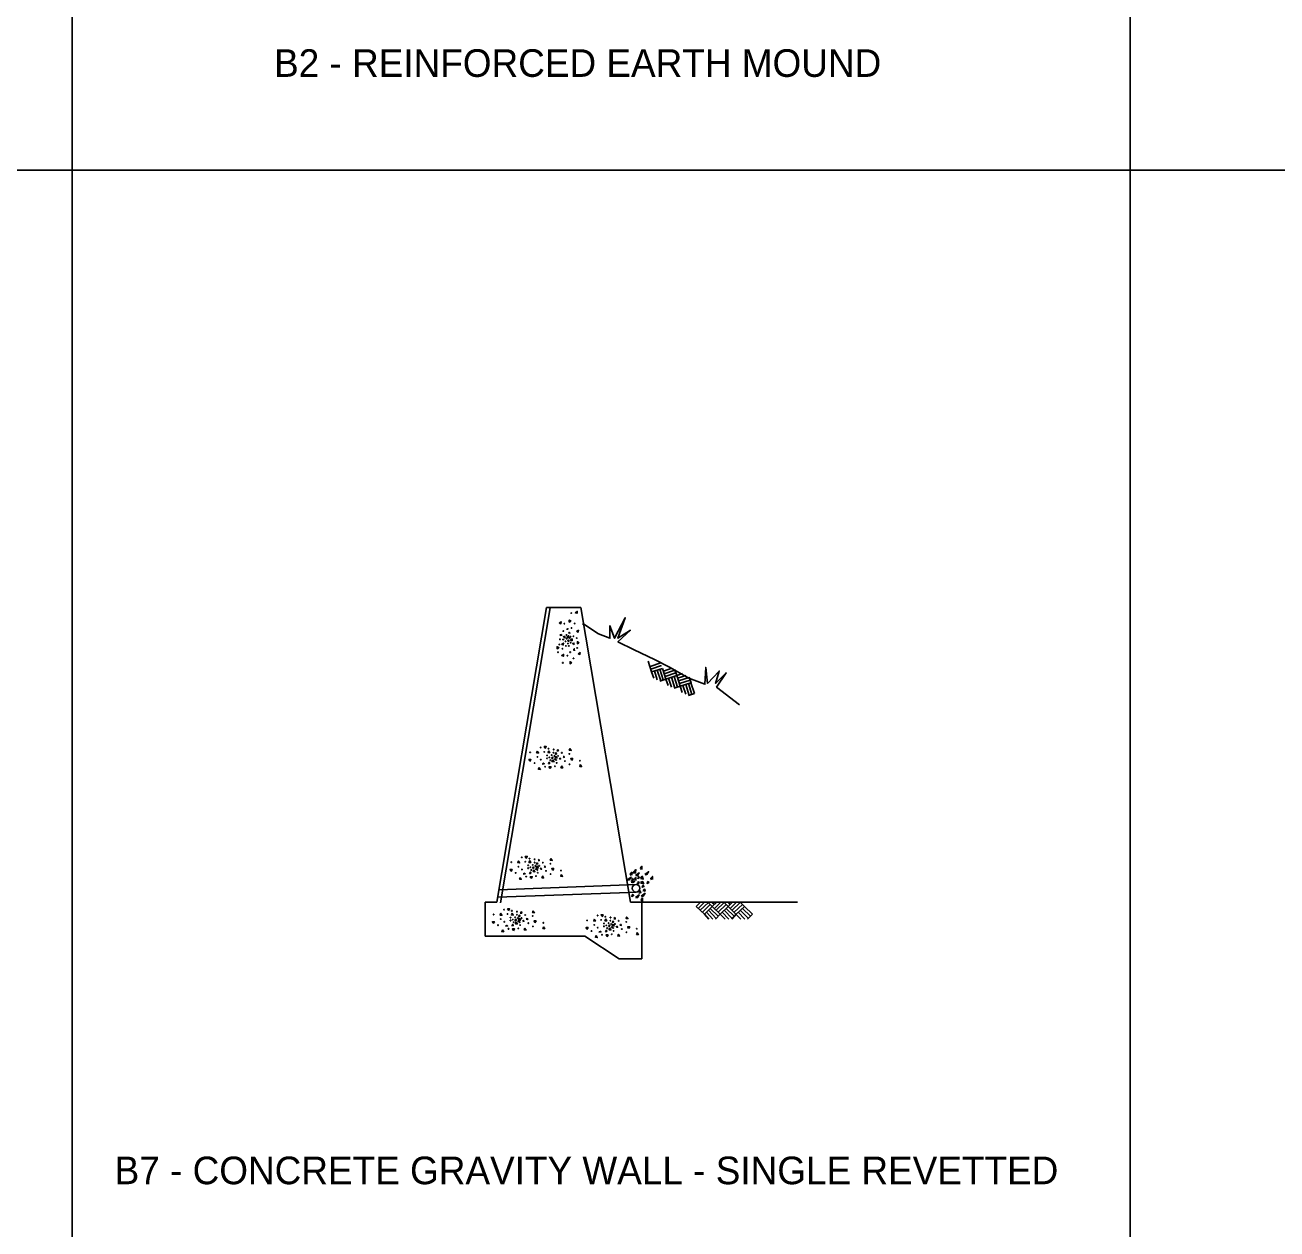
# Model space of a CAD drawing. Extents: x -0.04 to 2.79, y -0.02 to 1.81.
# Drawn here: x 0.5018 to 0.9741, y 0.915 to 1.369 of the extents above; entities that cross this region are included whole.
import ezdxf

# ---------------------------------------------------------------- set-up
doc = ezdxf.new("R2010")
doc.units = 0
doc.layers.add('Level 1', color=7, linetype='Continuous')
doc.layers.add('Level 2', color=7, linetype='Continuous')

msp = doc.modelspace()

# ---------------------------------------------------------------- linework, layer by layer
for p, q in [((0.51951, 1.73185), (0.51951, 0.08028)), ((0.91867, 1.71305), (0.91867, 0.08028)), ((0.11656, 1.31426), (2.51784, 1.31426))]:
    msp.add_line(p, q)
at = {"layer": 'Level 1'}
for p, q in [((0.67974, 1.03828), (0.69847, 1.14941)), ((0.68117, 1.03807), (0.6999, 1.14928)), ((0.69847, 1.14941), (0.71145, 1.14941)), ((0.73018, 1.03828), (0.71145, 1.14941)), ((0.71214, 1.14313), (0.71255, 1.14313)), ((0.73818, 1.12515), (0.73688, 1.12918)), ((0.73756, 1.12713), (0.74159, 1.1285)), ((0.73784, 1.12611), (0.74194, 1.12747)), ((0.73818, 1.12515), (0.74228, 1.12645)), ((0.739, 1.12276), (0.73818, 1.12515)), ((0.7403, 1.12207), (0.7392, 1.12549)), ((0.74159, 1.12173), (0.74023, 1.12576)), ((0.74255, 1.12207), (0.74125, 1.12611)), ((0.74358, 1.12242), (0.74228, 1.12645)), ((0.74262, 1.12542), (0.74576, 1.12652)), ((0.74289, 1.1244), (0.74699, 1.12576)), ((0.74324, 1.12344), (0.74734, 1.12474)), ((0.74768, 1.12371), (0.74693, 1.1259)), ((0.74768, 1.12371), (0.7498, 1.12447)), ((0.74768, 1.12371), (0.7498, 1.12447)), ((0.74125, 1.12166), (0.74358, 1.12242)), ((0.74358, 1.12242), (0.74768, 1.12371)), ((0.7444, 1.12002), (0.74358, 1.12242)), ((0.7457, 1.11941), (0.7446, 1.12276)), ((0.74693, 1.119), (0.74563, 1.1231)), ((0.74795, 1.11934), (0.74665, 1.12337)), ((0.74665, 1.11893), (0.74898, 1.11968)), ((0.74973, 1.11736), (0.74768, 1.12371)), ((0.74795, 1.12269), (0.75116, 1.12378)), ((0.74829, 1.12173), (0.75239, 1.12303)), ((0.74864, 1.12071), (0.75274, 1.122)), ((0.74898, 1.11968), (0.75301, 1.12098)), ((0.7511, 1.11667), (0.75, 1.12002)), ((0.75233, 1.11626), (0.75103, 1.12036)), ((0.75335, 1.11661), (0.75205, 1.12071)), ((0.75308, 1.12098), (0.75233, 1.12317)), ((0.75438, 1.11695), (0.75301, 1.12098)), ((0.75205, 1.1162), (0.75438, 1.11695)), ((0.68049, 1.04292), (0.72916, 1.04477)), ((0.72929, 1.04477), (0.73237, 1.04491)), ((0.68001, 1.04012), (0.72957, 1.04197)), ((0.72957, 1.04197), (0.73223, 1.0421)), ((0.67543, 1.03828), (0.67974, 1.03828)), ((0.67543, 1.02549), (0.67543, 1.03828)), ((0.73018, 1.03828), (0.73449, 1.03828)), ((0.73449, 1.01695), (0.73449, 1.03828)), ((0.73449, 1.03828), (0.79327, 1.03828)), ((0.75499, 1.0367), (0.75663, 1.03828)), ((0.75807, 1.0337), (0.75499, 1.0367)), ((0.75574, 1.03595), (0.75814, 1.03828)), ((0.7565, 1.0352), (0.75957, 1.03821)), ((0.75732, 1.03445), (0.76032, 1.03745)), ((0.75807, 1.0337), (0.76107, 1.0367)), ((0.76128, 1.03192), (0.75882, 1.03445)), ((0.76107, 1.0367), (0.75943, 1.03828)), ((0.76258, 1.03212), (0.75957, 1.0352)), ((0.76333, 1.03294), (0.76032, 1.03595)), ((0.76183, 1.03745), (0.76094, 1.03828)), ((0.76107, 1.0367), (0.76272, 1.03828)), ((0.76107, 1.0367), (0.76272, 1.03828)), ((0.76408, 1.0337), (0.76107, 1.0367)), ((0.76183, 1.03595), (0.76422, 1.03828)), ((0.76258, 1.03821), (0.76244, 1.03828)), ((0.76258, 1.0352), (0.76559, 1.03821)), ((0.76333, 1.03445), (0.76634, 1.03745)), ((0.76408, 1.0337), (0.76709, 1.0367)), ((0.76736, 1.03192), (0.76483, 1.03445)), ((0.76709, 1.0367), (0.76545, 1.03828)), ((0.76859, 1.03212), (0.76559, 1.0352)), ((0.76935, 1.03294), (0.76634, 1.03595)), ((0.76784, 1.03745), (0.76702, 1.03828)), ((0.76709, 1.0367), (0.76873, 1.03828)), ((0.76709, 1.0367), (0.76873, 1.03828)), ((0.77187, 1.03192), (0.76709, 1.0367)), ((0.76784, 1.03595), (0.77023, 1.03828)), ((0.76859, 1.03821), (0.76853, 1.03828)), ((0.76859, 1.0352), (0.7716, 1.03821)), ((0.76935, 1.03445), (0.77242, 1.03745)), ((0.7701, 1.0337), (0.77317, 1.0367)), ((0.77338, 1.03192), (0.77085, 1.03445)), ((0.77317, 1.0367), (0.77153, 1.03828)), ((0.77468, 1.03212), (0.7716, 1.0352)), ((0.77543, 1.03294), (0.77242, 1.03595)), ((0.77618, 1.0337), (0.77317, 1.0367)), ((0.75978, 1.03192), (0.75807, 1.0337)), ((0.76231, 1.03192), (0.76408, 1.0337)), ((0.76586, 1.03192), (0.76408, 1.0337)), ((0.76839, 1.03192), (0.7701, 1.0337)), ((0.7744, 1.03192), (0.77618, 1.0337)), ((0.67543, 1.02549), (0.71302, 1.02549)), ((0.72587, 1.01695), (0.71302, 1.02549)), ((0.72587, 1.01695), (0.73449, 1.01695))]:
    msp.add_line(p, q, dxfattribs=at)
for points in [[(0.71255, 1.14313), (0.71815, 1.1395), (0.72246, 1.13779), (0.72246, 1.14251), (0.72417, 1.13779), (0.7282, 1.14552), (0.72546, 1.13779), (0.73018, 1.1408), (0.72546, 1.1365), (0.73155, 1.13349), (0.7392, 1.1298), (0.74522, 1.12679), (0.75226, 1.12276), (0.75827, 1.12043), (0.75861, 1.12679), (0.7593, 1.12077), (0.76367, 1.12542), (0.76231, 1.12077), (0.76634, 1.12474), (0.76265, 1.11941), (0.77133, 1.11271)], [(0.73039, 1.04832), (0.73011, 1.04887), (0.73066, 1.04955), (0.73066, 1.04846)], [(0.73114, 1.04921), (0.73223, 1.05058), (0.73209, 1.04928), (0.73093, 1.04928)], [(0.73209, 1.04832), (0.73346, 1.04935), (0.73285, 1.04832), (0.73223, 1.04825)], [(0.73421, 1.05058), (0.73394, 1.05113), (0.73449, 1.05181), (0.73449, 1.05065)], [(0.73565, 1.04873), (0.73702, 1.04976), (0.7364, 1.04873), (0.73579, 1.0486)], [(0.72895, 1.04668), (0.73039, 1.04771), (0.7297, 1.04668), (0.72916, 1.04655)], [(0.73059, 1.04696), (0.73093, 1.04723), (0.73121, 1.04675), (0.73059, 1.04648), (0.73059, 1.04675)], [(0.73066, 1.04552), (0.73059, 1.04607), (0.73175, 1.04607), (0.73093, 1.04552)], [(0.73196, 1.04641), (0.73168, 1.04696), (0.73223, 1.04757), (0.73223, 1.04648)], [(0.73285, 1.04573), (0.73319, 1.046), (0.73346, 1.04552), (0.73285, 1.04525), (0.73285, 1.04552)], [(0.73291, 1.04771), (0.73326, 1.04798), (0.73353, 1.0475), (0.73291, 1.04723), (0.73291, 1.0475)], [(0.73401, 1.0473), (0.73462, 1.04805), (0.73503, 1.04696), (0.73394, 1.04723)], [(0.73401, 1.04566), (0.73476, 1.04607), (0.73517, 1.04525), (0.73394, 1.04552)], [(0.73462, 1.04429), (0.73496, 1.04463), (0.73524, 1.04415), (0.73462, 1.04388), (0.73462, 1.04415)], [(0.73647, 1.04579), (0.73681, 1.04607), (0.73708, 1.04566), (0.73647, 1.04532), (0.73647, 1.04566)], [(0.73818, 1.04675), (0.73784, 1.0473), (0.73845, 1.04798), (0.73845, 1.04682)], [(0.73066, 1.04094), (0.73107, 1.04121), (0.73134, 1.04074), (0.73066, 1.04046), (0.73066, 1.04074)], [(0.73209, 1.03998), (0.73346, 1.04108), (0.73285, 1.03998), (0.73223, 1.03992)], [(0.73346, 1.04217), (0.73387, 1.04244), (0.73414, 1.04197), (0.73346, 1.04169), (0.73346, 1.04197)], [(0.73449, 1.03862), (0.73421, 1.03916), (0.73476, 1.03985), (0.73476, 1.03869)], [(0.73428, 1.0406), (0.73572, 1.04162), (0.73503, 1.0406), (0.73449, 1.04046)], [(0.73503, 1.04285), (0.73565, 1.04313), (0.73572, 1.04244), (0.7349, 1.04272)]]:
    msp.add_lwpolyline(points, dxfattribs=at)
msp.add_circle((0.73229, 1.04352), 0.00141, dxfattribs=at)
at = {"layer": 'Level 2'}
for points in [[(0.70933, 1.14757), (0.71002, 1.14723), (0.71009, 1.14791), (0.70933, 1.14736)], [(0.70325, 1.1436), (0.70393, 1.14326), (0.704, 1.14401), (0.70325, 1.14347)], [(0.70769, 1.14422), (0.70708, 1.14388), (0.70708, 1.14463), (0.70783, 1.14422)], [(0.70359, 1.13909), (0.70414, 1.13916), (0.70414, 1.13868)], [(0.70393, 1.13868), (0.70359, 1.13909)], [(0.70551, 1.138), (0.70489, 1.13834), (0.7053, 1.13855), (0.70551, 1.138)], [(0.70612, 1.13834), (0.7068, 1.138), (0.70687, 1.13875), (0.70612, 1.1382)], [(0.70633, 1.14094), (0.70626, 1.14128), (0.7066, 1.14142), (0.70639, 1.14094)], [(0.70721, 1.13957), (0.70694, 1.13978), (0.70721, 1.14005), (0.70728, 1.13964)], [(0.70981, 1.14046), (0.7105, 1.14012), (0.71056, 1.1408), (0.70981, 1.14032)], [(0.70311, 1.13417), (0.7025, 1.13383), (0.7025, 1.13458), (0.70325, 1.13417)], [(0.70414, 1.13561), (0.70482, 1.13526), (0.70489, 1.13595), (0.70414, 1.13547)], [(0.70701, 1.13663), (0.70646, 1.13697), (0.70687, 1.13711), (0.70701, 1.13663)], [(0.70749, 1.13718), (0.70817, 1.13684), (0.70824, 1.13752), (0.70749, 1.13697)], [(0.70899, 1.13547), (0.70844, 1.13581), (0.70885, 1.13595), (0.70899, 1.13547)], [(0.70899, 1.13321), (0.70879, 1.13356), (0.70899, 1.13383), (0.70913, 1.13301)], [(0.71077, 1.13609), (0.71015, 1.13574), (0.71015, 1.1365), (0.71084, 1.13609)], [(0.70421, 1.13137), (0.70489, 1.13103), (0.70496, 1.13171), (0.70421, 1.13116)], [(0.70797, 1.1285), (0.70742, 1.12816), (0.70742, 1.12891), (0.7081, 1.1285)], [(0.71043, 1.13205), (0.71111, 1.13171), (0.71118, 1.13239), (0.71043, 1.13185)], [(0.69799, 1.09637), (0.69765, 1.09692), (0.6984, 1.09692), (0.69799, 1.09624)], [(0.70284, 1.09589), (0.70298, 1.09535), (0.70243, 1.09535)], [(0.70243, 1.09548), (0.70284, 1.09583)], [(0.70742, 1.09624), (0.70708, 1.09555), (0.70783, 1.09548), (0.70728, 1.09624)], [(0.69225, 1.09152), (0.6919, 1.09207), (0.69266, 1.09207), (0.69225, 1.09138)], [(0.69512, 1.09528), (0.69477, 1.0946), (0.69553, 1.09453), (0.69498, 1.09528)], [(0.69942, 1.09535), (0.69908, 1.09466), (0.69976, 1.0946), (0.69922, 1.09535)], [(0.70038, 1.09248), (0.70072, 1.09302), (0.70093, 1.09261), (0.70038, 1.09248)], [(0.70093, 1.092), (0.70058, 1.09132), (0.70134, 1.09125), (0.70079, 1.092)], [(0.70175, 1.09398), (0.70209, 1.0946), (0.70229, 1.09419), (0.70175, 1.09398)], [(0.70216, 1.09337), (0.70181, 1.09268), (0.7025, 1.09261), (0.70195, 1.09337)], [(0.70332, 1.09227), (0.70359, 1.09255), (0.70387, 1.09227), (0.70339, 1.0922)], [(0.70475, 1.09316), (0.7051, 1.09323), (0.70523, 1.09289), (0.70475, 1.09309)], [(0.70803, 1.09179), (0.70769, 1.09241), (0.70844, 1.09241), (0.70803, 1.09166)], [(0.6958, 1.08906), (0.69546, 1.08838), (0.69621, 1.08831), (0.69566, 1.08906)], [(0.69696, 1.0905), (0.6973, 1.0907), (0.69765, 1.0905), (0.69683, 1.09036)], [(0.69922, 1.0905), (0.69956, 1.09104), (0.69976, 1.09063), (0.69922, 1.0905)], [(0.69983, 1.08872), (0.69949, 1.08933), (0.70024, 1.08933), (0.69983, 1.08865)], [(0.70428, 1.08967), (0.70393, 1.08899), (0.70462, 1.08892), (0.70414, 1.08967)], [(0.71138, 1.09015), (0.71104, 1.08947), (0.71173, 1.0894), (0.71118, 1.09015)], [(0.68801, 1.05386), (0.68767, 1.05318), (0.68835, 1.05311), (0.6878, 1.05386)], [(0.69081, 1.05488), (0.69047, 1.0555), (0.69122, 1.0555), (0.69081, 1.05475)], [(0.69225, 1.05393), (0.6919, 1.05324), (0.69259, 1.05318), (0.69211, 1.05393)], [(0.69532, 1.05406), (0.69573, 1.05441)], [(0.69573, 1.05441), (0.6958, 1.05393), (0.69532, 1.05393)], [(0.70024, 1.05475), (0.6999, 1.05406), (0.70065, 1.054), (0.70011, 1.05475)], [(0.68514, 1.05003), (0.6848, 1.05065), (0.68555, 1.05065), (0.68514, 1.04989)], [(0.68985, 1.04901), (0.6902, 1.04921), (0.69047, 1.04901), (0.68965, 1.04887)], [(0.69211, 1.04901), (0.69245, 1.04962), (0.69259, 1.04921), (0.69211, 1.04901)], [(0.69327, 1.05099), (0.69361, 1.0516), (0.69375, 1.05119), (0.69327, 1.05099)], [(0.69382, 1.05051), (0.69348, 1.04983), (0.69416, 1.04976), (0.69361, 1.05051)], [(0.69464, 1.05256), (0.69498, 1.05311), (0.69518, 1.0527), (0.69464, 1.05256)], [(0.69498, 1.05195), (0.69464, 1.05126), (0.69539, 1.05119), (0.69484, 1.05195)], [(0.69621, 1.05078), (0.69641, 1.05113), (0.69669, 1.05078), (0.69628, 1.05078)], [(0.69758, 1.05167), (0.69792, 1.05181), (0.69806, 1.05147), (0.69758, 1.0516)], [(0.70086, 1.0503), (0.70052, 1.05092), (0.70127, 1.05092), (0.70086, 1.05024)], [(0.70421, 1.04873), (0.70387, 1.04805), (0.70455, 1.04798), (0.704, 1.04873)], [(0.68869, 1.04764), (0.68835, 1.04696), (0.68903, 1.04689), (0.68849, 1.04764)], [(0.69272, 1.0473), (0.69238, 1.04784), (0.69313, 1.04784), (0.69272, 1.04716)], [(0.6971, 1.04819), (0.69676, 1.0475), (0.69744, 1.04743), (0.69696, 1.04819)], [(0.68418, 1.0352), (0.68384, 1.03575), (0.68459, 1.03575), (0.68418, 1.03506)], [(0.68903, 1.03472), (0.68917, 1.03417), (0.68862, 1.03417)], [(0.68862, 1.03431), (0.68903, 1.03465)], [(0.69361, 1.03506), (0.69327, 1.03438), (0.69395, 1.03431), (0.69341, 1.03506)], [(0.67844, 1.03035), (0.6781, 1.03089), (0.67885, 1.03089), (0.67844, 1.03021)], [(0.68131, 1.03411), (0.68097, 1.03342), (0.68172, 1.03335), (0.68117, 1.03411)], [(0.68562, 1.03417), (0.68527, 1.03349), (0.68596, 1.03342), (0.68541, 1.03417)], [(0.68541, 1.02932), (0.68575, 1.02987), (0.68596, 1.02946), (0.68541, 1.02932)], [(0.68657, 1.0313), (0.68691, 1.03185), (0.68712, 1.03144), (0.68657, 1.0313)], [(0.68712, 1.03082), (0.68678, 1.03014), (0.68753, 1.03007), (0.68698, 1.03082)], [(0.68794, 1.03281), (0.68828, 1.03342), (0.68849, 1.03301), (0.68794, 1.03281)], [(0.68835, 1.03219), (0.68801, 1.03151), (0.68869, 1.03144), (0.68814, 1.03219)], [(0.68951, 1.0311), (0.68978, 1.03137), (0.69006, 1.0311), (0.68958, 1.03103)], [(0.69088, 1.03199), (0.69122, 1.03206), (0.69143, 1.03171), (0.69088, 1.03192)], [(0.69416, 1.03062), (0.69382, 1.03123), (0.69457, 1.03123), (0.69416, 1.03048)], [(0.71665, 1.03192), (0.71631, 1.03123), (0.71699, 1.03117), (0.71644, 1.03192)], [(0.71945, 1.03294), (0.71911, 1.03356), (0.71986, 1.03356), (0.71945, 1.03281)], [(0.72088, 1.03199), (0.72054, 1.0313), (0.72123, 1.03123), (0.72075, 1.03199)], [(0.72328, 1.03062), (0.72362, 1.03117), (0.72382, 1.03076), (0.72328, 1.03062)], [(0.72362, 1.03), (0.72328, 1.02932), (0.72403, 1.02925), (0.72348, 1.03)], [(0.72396, 1.03212), (0.72437, 1.03247)], [(0.72437, 1.03247), (0.72444, 1.03199), (0.72396, 1.03199)], [(0.72622, 1.02973), (0.72656, 1.02987), (0.72669, 1.02953), (0.72622, 1.02966)], [(0.72888, 1.03281), (0.72854, 1.03212), (0.72929, 1.03206), (0.72874, 1.03281)], [(0.68199, 1.02789), (0.68165, 1.0272), (0.6824, 1.02713), (0.68186, 1.02789)], [(0.68315, 1.02932), (0.6835, 1.02953), (0.68384, 1.02932), (0.68302, 1.02918)], [(0.68603, 1.02754), (0.68568, 1.02816), (0.68644, 1.02816), (0.68603, 1.02748)], [(0.69047, 1.0285), (0.69013, 1.02782), (0.69081, 1.02775), (0.69026, 1.0285)], [(0.69751, 1.02898), (0.69717, 1.0283), (0.69785, 1.02823), (0.69737, 1.02898)], [(0.71378, 1.02809), (0.71343, 1.02871), (0.71419, 1.02871), (0.71378, 1.02795)], [(0.71733, 1.0257), (0.71699, 1.02502), (0.71767, 1.02495), (0.71713, 1.0257)], [(0.71849, 1.02707), (0.71883, 1.02727), (0.71911, 1.02707), (0.71829, 1.02693)], [(0.72075, 1.02707), (0.72109, 1.02768), (0.72123, 1.02727), (0.72075, 1.02707)], [(0.72136, 1.02536), (0.72102, 1.0259), (0.72177, 1.0259), (0.72136, 1.02522)], [(0.72191, 1.02905), (0.72225, 1.02966), (0.72239, 1.02925), (0.72191, 1.02905)], [(0.72246, 1.02857), (0.72211, 1.02789), (0.7228, 1.02782), (0.72225, 1.02857)], [(0.72485, 1.02884), (0.72505, 1.02918), (0.72533, 1.02884), (0.72492, 1.02884)], [(0.72574, 1.02625), (0.7254, 1.02556), (0.72608, 1.02549), (0.7256, 1.02625)], [(0.7295, 1.02836), (0.72916, 1.02898), (0.72991, 1.02898), (0.7295, 1.0283)], [(0.73285, 1.02679), (0.7325, 1.02611), (0.73319, 1.02604), (0.73264, 1.02679)]]:
    msp.add_lwpolyline(points, dxfattribs=at)
for centre in [(0.70526, 1.14331), (0.70784, 1.14729), (0.70917, 1.14338), (0.70486, 1.14049), (0.70606, 1.13906), (0.70756, 1.13837), (0.70796, 1.14166), (0.70866, 1.13855), (0.70331, 1.13544), (0.7036, 1.13738), (0.70451, 1.13383), (0.7048, 1.13733), (0.70572, 1.13665), (0.70584, 1.13492), (0.70606, 1.13767), (0.70659, 1.13578), (0.70693, 1.13492), (0.70727, 1.13785), (0.70762, 1.13612), (0.70992, 1.13786), (0.71009, 1.13417), (0.70285, 1.13251), (0.7064, 1.13125), (0.70745, 1.13257), (0.70871, 1.13021), (0.70468, 1.12853), (0.69633, 1.0966), (0.69925, 1.09614), (0.7012, 1.09585), (0.69235, 1.09478), (0.69507, 1.09305), (0.69638, 1.09201), (0.69765, 1.09495), (0.69874, 1.09361), (0.69874, 1.09252), (0.69959, 1.09286), (0.69994, 1.09184), (0.70046, 1.09373), (0.70115, 1.09466), (0.70149, 1.09339), (0.70166, 1.09218), (0.70219, 1.09189), (0.70287, 1.09339), (0.70431, 1.09459), (0.70547, 1.09149), (0.70713, 1.09419), (0.71111, 1.09161), (0.69402, 1.09074), (0.69799, 1.08936), (0.70168, 1.08953), (0.70236, 1.09079), (0.7072, 1.09028), (0.68521, 1.05336), (0.68919, 1.05518), (0.6905, 1.05353), (0.69211, 1.05472), (0.69401, 1.05324), (0.69406, 1.05443), (0.68688, 1.04932), (0.68792, 1.05163), (0.68924, 1.05059), (0.6916, 1.05219), (0.6916, 1.0511), (0.69245, 1.05144), (0.69279, 1.05042), (0.69332, 1.05231), (0.69435, 1.05197), (0.69452, 1.05076), (0.69505, 1.05047), (0.69522, 1.04937), (0.69573, 1.05197), (0.69717, 1.05317), (0.69833, 1.05007), (0.69999, 1.05277), (0.70005, 1.04886), (0.70397, 1.05019), (0.69084, 1.04794), (0.69454, 1.04811), (0.68252, 1.03546), (0.68544, 1.035), (0.68739, 1.03471), (0.67854, 1.03364), (0.68022, 1.0296), (0.68126, 1.03191), (0.68257, 1.03087), (0.68384, 1.03381), (0.68493, 1.03247), (0.68493, 1.03138), (0.68579, 1.03172), (0.68613, 1.0307), (0.68666, 1.03259), (0.68734, 1.03352), (0.68768, 1.03225), (0.68785, 1.03104), (0.68838, 1.03075), (0.68855, 1.02965), (0.68907, 1.03225), (0.6905, 1.03345), (0.69166, 1.03035), (0.69332, 1.03305), (0.6973, 1.03047), (0.71381, 1.03141), (0.71653, 1.02969), (0.71779, 1.03324), (0.71911, 1.03159), (0.7202, 1.03025), (0.72071, 1.03278), (0.72193, 1.03037), (0.72261, 1.03129), (0.72266, 1.03249), (0.72295, 1.03003), (0.72434, 1.03003), (0.72577, 1.03123), (0.72859, 1.03083), (0.68418, 1.02822), (0.68787, 1.02839), (0.69339, 1.02914), (0.71548, 1.02738), (0.71784, 1.02865), (0.71945, 1.026), (0.7202, 1.02916), (0.72106, 1.0295), (0.7214, 1.02848), (0.72312, 1.02882), (0.72314, 1.02617), (0.72365, 1.02853), (0.72382, 1.02743), (0.72693, 1.02813), (0.72866, 1.02692), (0.73257, 1.02825)]:
    msp.add_circle(centre, 0.000111, dxfattribs=at)

# ---------------------------------------------------------------- texts
for s, p in [('B2 - REINFORCED EARTH MOUND', (0.59573, 1.3495)), ('B7 - CONCRETE GRAVITY WALL - SINGLE REVETTED', (0.53558, 0.93191))]:
    msp.add_text(s, height=0.0104167).set_placement(p)

doc.saveas('drawing.dxf')
